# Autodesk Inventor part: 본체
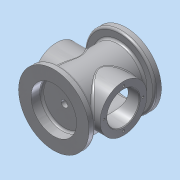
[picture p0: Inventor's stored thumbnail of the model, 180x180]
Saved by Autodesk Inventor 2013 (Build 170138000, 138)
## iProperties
Created: 2018-02
Part Number: 본체
Material: 알루미늄 6061
Document SubType Name: Modeling
Designer: dgall
Density: 2.71 g/cm^3
Mass: 771.855 g
Surface Area: 821.791 cm^2
Volume: 284.817 cm^3
Author: dgall
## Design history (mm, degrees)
sketch "스케치1"
  geometry: L1 (0, 0)-(0, 108); L2 (0, 108)-(-52.5, 108); L3 (-52.5, 108)-(-52.5, 98); L4 (-52.5, 98)-(-38, 98); L5 (-38, 98)-(-38, 10); L6 (-38, 10)-(-52.5, 10); L7 (-52.5, 10)-(-52.5, 0); L8 (-52.5, 0)-(0, 0)
  constraints: 16 end point, 4 perpendicular, 3 parallel, 2 equal length, 1 vertical, 1 vertical alignment
  dimensions: "d5" = 108 distance of L1.start L1.end; "d7" = 105 diameter of L3 L1; "d8" = 10 distance of L2.end L3.end; "d9" = 76 diameter of L5 L1
revolve "회전1" sketch "스케치1" stored, may be unused: angle "d10" = 90 deg
node "작업 평면1"
sketch "스케치2"
  geometry: L1 (-108, 52.5)-(-108, -52.5) reference; L2 (-10, 38)-(-98, 38) reference; C1 r 35 at (-54, 0); 3 further points
  constraints: 2 midpoint, 1 centre point, 1 horizontal alignment, 1 vertical alignment
  dimensions: "d12" = 35 radius of C1
extrude "돌출1" join sketch "스케치2" stored distance "d13" = 10; taper "d14" = 0 deg
sketch "스케치3" dims "d15" = 29
  geometry: C1 r 35 at (0, 0) reference; C2 r 24 at (0, 0); 3 further points
  constraints: 2 coincident, 2 horizontal alignment, 1 centre point, 2 other
  dimensions: "d16" = 24 radius of C2
sketch "스케치4"
  geometry: C1 r 52.5 at (0, 0) reference; C2 r 37 at (0, 0)
  constraints: 1 centre point, 1 coincident
  dimensions: "d17" = 37 radius of C2
extrude "돌출2" cut sketch "스케치4" distance "d18" = 7; taper "d19" = 0 deg
sketch "스케치5"
  geometry: C1 r 37 at (0, 0) reference; C2 r 33 at (0, 0)
  constraints: 1 centre point, 1 coincident
  dimensions: "d20" = 33 radius of C2
extrude "돌출3" cut sketch "스케치5" distance "d21" = 79; taper "d22" = 0 deg
sketch "스케치6"
  geometry: C1 r 52.5 at (0, 0) reference; C2 r 34 at (0, 0)
  constraints: 1 centre point, 1 coincident
  dimensions: "d23" = 34 radius of C2
extrude "돌출4" cut sketch "스케치6" distance "d24" = 16; taper "d25" = 0 deg
sketch "스케치7"
  geometry: C1 r 34 at (0, 0) reference; C2 r 5 at (0, 0)
  constraints: 1 centre point, 1 coincident
  dimensions: "d26" = 5 radius of C2
extrude "돌출5" cut sketch "스케치7" stored distance "d27" = 16; taper "d28" = 0 deg
extrude "돌출6" cut sketch "스케치3" stored distance "d29" = 16; taper "d30" = 0 deg
hole "구멍1" sketch "스케치3" diameter "d31" = 3.242; stored, may be unused: countersink angle "d35" = 90 deg, drill point angle "d37" = 118 deg; dims "d32" = 4, "d33" = 4, "d34" = 2, "d36" = 6
chamfer "모따기1" distance "d41" = 1; stored, may be unused: second distance "d42" = 2, angle "d43" = 45 deg
fillet "모깎기1" dims "d44" = 3
fillet "모깎기2" dims "d45" = 3
chamfer "모따기2" distance "d46" = 1; stored, may be unused: second distance "d47" = 2, angle "d48" = 45 deg
chamfer "모따기3" distance "d49" = 1; stored, may be unused: second distance "d50" = 2, angle "d51" = 45 deg
sketch "스케치8" dims "d52" = 45
  geometry: C1 r 52.5 at (0, 0) reference; C2 r 38 at (0, 0) reference; 2 further points
  constraints: 2 vertical alignment, 1 coincident, 2 other
hole "구멍2" sketch "스케치8" at (0, 45) diameter "d53" = 3.242; stored, may be unused: countersink angle "d57" = 90 deg, drill point angle "d59" = 118 deg; dims "d54" = 4, "d55" = 4, "d56" = 2, "d58" = 6
fillet "모깎기3" dims "d63" = 3
fillet "모깎기4" dims "d64" = 3
node "작업 평면2"
sketch "스케치9"
  geometry: L1 (-7, 67)-(-7, 41); L2 (7, 67)-(7, 41); L3 (-50, 89)-(-50, 19) reference; L4 (52.5, 108)-(-52.5, 108) reference; A1 r 7 centre (0, 67) between (7, 67) and (-7, 67); A2 r 7 centre (0, 41) between (-7, 41) and (7, 41); 4 further points
  constraints: 4 end point, 4 point on circle, 3 midpoint, 2 centre point, 2 tangent, 2 vertical alignment, 1 horizontal alignment, 1 parallel
  dimensions: "d66" = 7 radius of A1; "d67" = 7 radius of A2; "d70" = 13 vertical distance of A1.centre point (-7, 54); "d71" = 13 vertical distance of A2.centre point (-7, 54)
extrude "돌출7" join sketch "스케치9" stored distance "d72" = 16; taper "d73" = 15 deg
sketch "스케치10"
  geometry: A1 r 7 centre (0, 67) between (7, 67) and (-7, 67) reference; A2 r 7 centre (0, 41) between (-7, 41) and (7, 41) reference; 3 further points
  constraints: 2 coincident
hole "구멍3" sketch "스케치10" at (0, 67), (0, 41) diameter "d74" = 4.134; stored, may be unused: countersink angle "d78" = 90 deg, drill point angle "d80" = 118 deg; dims "d75" = 6, "d76" = 4, "d77" = 2, "d79" = 8
fillet "모깎기5" dims "d81" = 3
sketch "스케치11"
  geometry: C1 r 49.5 at (0, 0) reference; 1 further point
  constraints: 1 vertical alignment, 1 other
  dimensions: "d82" = 45 distance of point (0, 45) C1.centre
feature "엠보싱1" sketch "스케치11" dims "d5" = 108, "d7" = 105, "d8" = 10, "d9" = 76, "d84" = 0.5, "d85" = 0
node "솔리드1"
pattern_circular "원형 패턴1" dims angle "d39" = 360 deg
mirror "대칭1"
pattern_circular "원형 패턴2" dims angle "d61" = 360 deg
other parameters: "d65" = -55
